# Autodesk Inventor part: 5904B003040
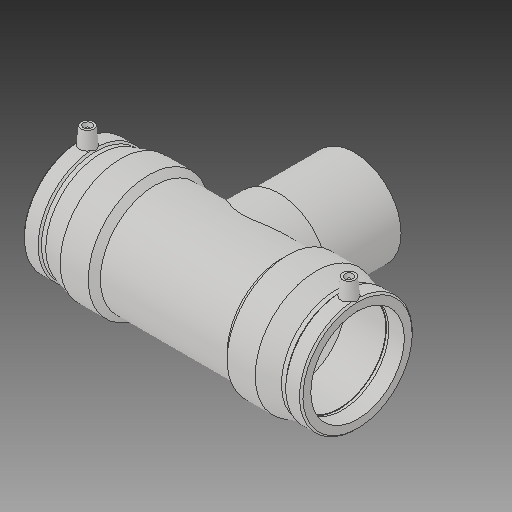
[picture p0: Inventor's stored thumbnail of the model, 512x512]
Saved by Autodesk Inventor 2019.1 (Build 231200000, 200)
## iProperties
Created: 2017-06
Part Number: 5904B003040
Material: Generic
Description: PLASSON TEE 4''IPS
Document SubType Name: Modeling
Designer: KIM
Mass: 17327.5 g
Surface Area: 12195.1 cm^2
Volume: 17327.5 cm^3
Density: 1 g/cm^3
Appearance: Default
Author: KIM
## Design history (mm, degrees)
derived "5904B.ipt"
feature "Solid1::5904B.ipt"
tag "TaggingFeature1"
body "Solid1"
other parameters: "L_" = 327.66, "L_1" = 69.596, "D_" = 142.494, "A_" = 85.598, "d_2" = 12, "H_" = 160.02, "d0" = 327.66, "d2" = 142.494, "d3" = 69.596, "d4" = 81.915, "d5" = 128.2446, "d6" = 104.5, "d8" = 168 deg, "d10" = 27.8384, "d11" = 9.27947, "d13" = 327.66, "d14" = 17.6296, "d17" = 99, "d19" = 3.52592, "d20" = 168 deg, "d22" = 132.51942, "d23" = 142.494, "d24" = 128.54384, "d25" = 135 deg, "d26" = 229.362, "d27" = 135 deg, "d29" = 85.598, "d30" = 15, "d31" = 131.064, "d34" = 5 deg, "d35" = 15, "d39" = 5 deg, "d40" = 9.6, "d41" = 4.8, "d42" = 6, "d43" = 0, "d45" = 4, "d46" = 14, "d47" = 0, "d48" = -160.02, "d51" = 0, "d52" = 88, "d54" = 0, "d55" = 128.2446, "d56" = 142.494, "d57" = 114.681, "d58" = 135 deg, "d59" = 69.596, "d60" = 69.596, "d61" = 135 deg, "d62" = 160.02, "d72" = 149.0853, "d73" = 74.54265, "d74" = -160.02, "d75" = 115.5, "d77" = 0, "d78" = 88, "d80" = 0, "d82" = 88.773, "d83" = 0, "d84" = 3, "d85" = 0, "d86" = 3, "d87" = 0, "d88" = 20.18284, "d89" = 5.04571, "d90" = 20.18284
